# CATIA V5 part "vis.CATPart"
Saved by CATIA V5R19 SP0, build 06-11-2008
Part number: vis CH102008
Bounding box of the stored display mesh (mm): x 0 to 10, y -1.9 to 1.9, z -1.9 to 1.9
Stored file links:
  I:\mediator\vis.CATPart
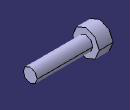
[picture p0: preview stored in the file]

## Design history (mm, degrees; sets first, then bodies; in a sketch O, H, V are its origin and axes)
Body1 (main body)
  Sketch1 on yz-plane, origin (0, 0, 0), H (0, 1, 0), V (0, 0, 1)
    circle A1 centre (0, 0) radius 1.9
    radius A1 = 1.9
  Pad1: profile Sketch1, direction (1, 0, 0), length 2
  Sketch2 on end face of Pad1, origin (2, 0, 0), H (0, 1, 0), V (0, 0, 1)
    circle A1 centre (0, 0) radius 1
    radius A1 = 1
  Pad2: profile Sketch2, direction (1, 0, 0), length 8
  Sketch3 on start face of Pad1, origin (0, 0, 0), H (0, -1, 0), V (0, 0, 1)
    point P1 (0.6491, -0.3757)
    line L1 (0.6491, -0.3757) -> (0.6491, 0.3757)
    point P2 (0.6491, 0.3757)
    line L2 (0.6491, 0.3757) -> (0, 0.75)
    point P3 (0, 0.75)
    line L3 (0.6491, -0.3757) -> (0, -0.75)
    point P4 (0, -0.75)
    axis line L4 (0, 1.1732) -> (0, -1.4036)
    point P5 (0, 1.1732)
    point P7 (0, -0.75)
    point P8 (-0.6491, -0.3757)
    line L5 (-0.6491, -0.3757) -> (0, -0.75)
    point P9 (-0.6491, 0.3757)
    line L6 (-0.6491, -0.3757) -> (-0.6491, 0.3757)
    point P10 (0, 0.75)
    line L7 (-0.6491, 0.3757) -> (0, 0.75)
    vertical: L1 V, L4 V
    coincidence: P3 V, P4 V, P5 V, P3 P10, P4 P7
    symmetry: P4 P7 L4, P1 P8 L4, L3 L5 L4, P2 P9 L4, L1 L6 L4, P3 P10 L4, L2 L7 L4
  Pocket1: profile Sketch3, direction (1, 0, 0), length 1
